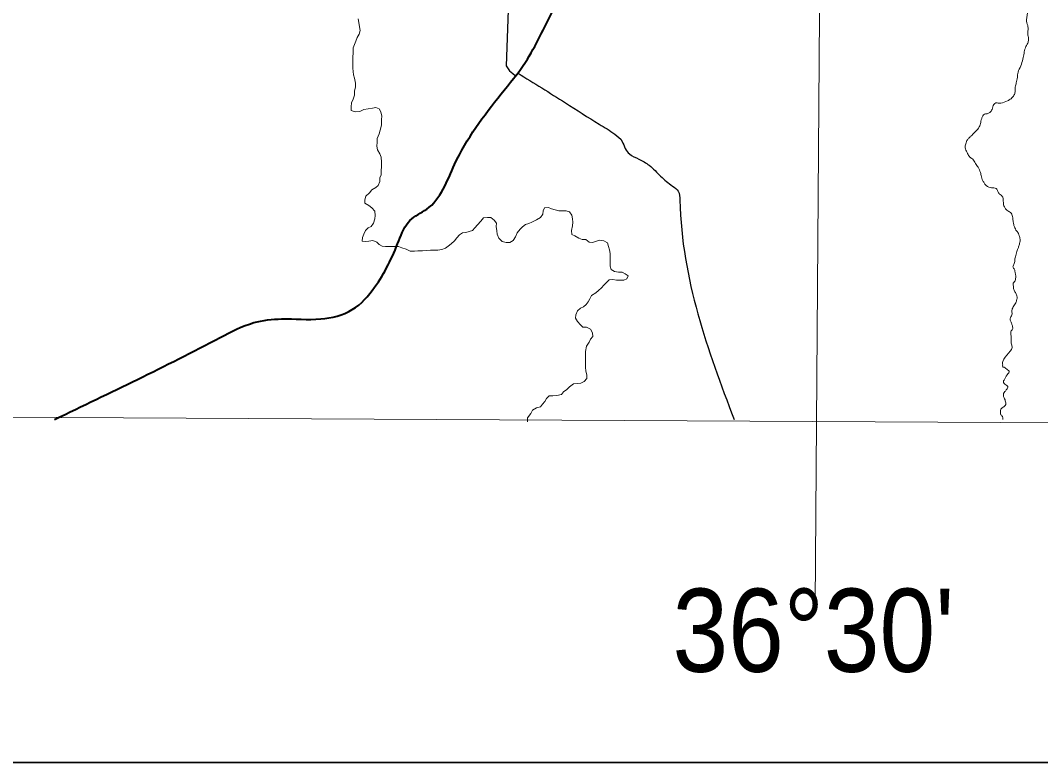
# Model space of a CAD drawing. Extents: x 553962 to 842807, y 8883888 to 9032388.
# Drawn here: x 616084 to 619151, y 8897728 to 8899960 of the extents above; entities that cross this region are included whole.
import ezdxf
from ezdxf.enums import TextEntityAlignment as Align

# ---------------------------------------------------------------- set-up
doc = ezdxf.new("R2010")
doc.units = 0
doc.header["$LTSCALE"] = 160
doc.layers.add('6', color=7, linetype='Continuous', lineweight=13)

msp = doc.modelspace()

# ---------------------------------------------------------------- linework, layer by layer
at = {"layer": '6', "lineweight": 35}
msp.add_lwpolyline([(576104.8, 8927170.9), (624533.7, 8927170.9), (624533.7, 8897728.1), (576104.8, 8897728.1)], close=True, dxfattribs=at)
at = {"layer": '6'}
for points in [[(618663, 8924716.1), (618558.3, 8909803.7), (618472.6, 8898203.5)], [(617099.6, 8899964.4), (617105.5, 8899929.8), (617102.3, 8899918.6), (617096.2, 8899908.4), (617092, 8899897.3), (617087.9, 8899887.1), (617083.7, 8899876.9), (617083.7, 8899865.7), (617083.5, 8899846.4), (617083.5, 8899836.2), (617083.4, 8899826), (617083.3, 8899815.8), (617085.2, 8899796.4), (617088.2, 8899786.2), (617091.1, 8899770.9), (617091.1, 8899759.7), (617087.9, 8899747.5), (617087.8, 8899735.3), (617083.7, 8899723.1), (617079.5, 8899711.9), (617078.4, 8899699.7), (617078.4, 8899688.5), (617090.6, 8899685.4), (617103.8, 8899686.3), (617116, 8899692.3), (617129.3, 8899694.3), (617142.5, 8899696.2), (617152.7, 8899698.2), (617161.8, 8899694.1), (617166.8, 8899684.9), (617169.8, 8899671.6), (617169.7, 8899661.4), (617169.6, 8899645.1), (617165.4, 8899629.9), (617162.3, 8899618.7), (617156.1, 8899604.5), (617156, 8899593.3), (617154.9, 8899582.1), (617156.9, 8899570.8), (617163.9, 8899558.6), (617167.9, 8899548.4), (617168.8, 8899533.1), (617168.8, 8899520.8), (617168.7, 8899507.6), (617168.6, 8899495.4), (617164.5, 8899486.2)], [(617164.5, 8899486.2), (617164.4, 8899475), (617159.5, 8899463.6), (617151.9, 8899457.9), (617139.8, 8899450.7), (617133.6, 8899441.6), (617122.4, 8899431.5), (617119.2, 8899420.3), (617119.2, 8899410.1), (617131.3, 8899402.9), (617140.4, 8899396.7), (617149.5, 8899386.5), (617150.5, 8899373.2), (617149.4, 8899363.1), (617145.2, 8899349.8), (617138, 8899339.7), (617128.8, 8899335.7), (617120.7, 8899328.6), (617116.5, 8899317.4), (617112.4, 8899307.3), (617111.3, 8899296.1), (617121.4, 8899295), (617131.6, 8899295.9), (617142.8, 8899297.9), (617155, 8899292.7), (617162.1, 8899285.6), (617171.2, 8899281.4), (617181.3, 8899280.3), (617195.6, 8899280.2), (617205.8, 8899280.2), (617220, 8899280.1), (617230.2, 8899275.9), (617243.3, 8899271.8), (617255.5, 8899265.6), (617268.7, 8899265.5), (617278.9, 8899266.5), (617292.1, 8899267.4)], [(617292.1, 8899267.4), (617304.3, 8899268.3), (617316.6, 8899269.3), (617327.8, 8899269.2), (617338.9, 8899269.1), (617350.2, 8899271.1), (617361.4, 8899275.1), (617369.5, 8899281.2), (617378.8, 8899288.2), (617389, 8899297.3), (617396.2, 8899306.5), (617403.3, 8899314.6), (617412.5, 8899320.6), (617422.7, 8899321.6), (617432.9, 8899325.6), (617443.1, 8899328.6), (617450.3, 8899335.7), (617457.5, 8899344.8), (617467.7, 8899355.9), (617475.9, 8899366.1), (617488.1, 8899367), (617498.3, 8899366.9), (617508.4, 8899358.7), (617514.5, 8899350.5), (617514.4, 8899340.3), (617516.3, 8899327.1), (617517.3, 8899316.9), (617522.3, 8899304.6), (617532.4, 8899295.4), (617543.6, 8899292.3), (617554.8, 8899292.2), (617565, 8899298.2), (617572.2, 8899309.4), (617577.3, 8899320.6), (617585.6, 8899331.7), (617592.7, 8899338.8), (617601.9, 8899345.9), (617612.1, 8899348.9), (617621.3, 8899352.9), (617635.6, 8899359.9), (617646.8, 8899367), (617654, 8899377.1), (617655.1, 8899387.3), (617659.2, 8899396.5), (617671.4, 8899397.4), (617680.6, 8899393.3), (617691.7, 8899390.1), (617701.9, 8899387), (617713.1, 8899386.9), (617724.3, 8899386.9), (617734.4, 8899383.8), (617741.5, 8899374.5), (617743.4, 8899363.3), (617744.4, 8899353.1), (617743.3, 8899341.9), (617740.1, 8899327.7), (617741.1, 8899316.5), (617750.2, 8899312.3), (617762.4, 8899305.1), (617772.5, 8899301), (617783.7, 8899300.9), (617793.8, 8899292.7), (617804, 8899291.6), (617815.2, 8899295.6), (617825.4, 8899298.6)], [(617825.4, 8899298.6), (617837.6, 8899297.5), (617848.7, 8899291.3), (617851.7, 8899280.1), (617854.7, 8899269.9), (617856.6, 8899258.7), (617856.6, 8899244.4), (617856.5, 8899233.2), (617856.4, 8899221), (617859.4, 8899210.8), (617869.5, 8899204.6), (617881.7, 8899202.5), (617892.9, 8899202.4), (617902, 8899198.3), (617911.1, 8899192.1), (617907, 8899183), (617897.8, 8899178.9), (617885.6, 8899179), (617875.4, 8899179.1), (617864.2, 8899181.2), (617854.1, 8899180.2), (617844.8, 8899171.1), (617837.7, 8899164.1), (617830.5, 8899155.9), (617821.3, 8899147.9), (617813.1, 8899140.8), (617800.8, 8899132.7), (617795.7, 8899122.6), (617790.5, 8899113.4), (617784.4, 8899105.3), (617776.2, 8899098.2), (617767, 8899094.2), (617758.8, 8899086.1), (617753.7, 8899074.9), (617752.6, 8899064.8), (617758.6, 8899054.5), (617767.7, 8899044.3)], [(617767.7, 8899044.3), (617774.8, 8899037.1), (617786, 8899037), (617797.1, 8899031.9), (617803.1, 8899020.6), (617804.1, 8899009.4), (617797.9, 8899001.3), (617793.8, 8898992.2), (617785.6, 8898980), (617782.4, 8898964.7), (617782.3, 8898952.5), (617782.2, 8898940.3), (617782.2, 8898928.1), (617782.1, 8898916.8), (617783, 8898905.6), (617787, 8898894.4), (617786.9, 8898883.2), (617778.7, 8898874.1), (617768.5, 8898869.1), (617757.3, 8898868.1), (617746.1, 8898867.2), (617733.9, 8898858.1), (617726.7, 8898850), (617716.5, 8898842.9), (617710.3, 8898834.8), (617696, 8898831.8), (617683.8, 8898830.9), (617673.7, 8898830.9), (617665.5, 8898822.9), (617660.3, 8898813.7), (617653.1, 8898805.6), (617647, 8898797.5), (617634.8, 8898794.5), (617623.5, 8898787.5), (617618.4, 8898778.3), (617608.1, 8898765.2), (617608, 8898753.2), (617608, 8898753.2), (617608.1, 8898765.2)], [(577181.5, 8898943.8), (596544.3, 8898870.4), (623547.8, 8898727.2)]]:
    msp.add_lwpolyline(points, dxfattribs=at)
at = {"layer": '6', "lineweight": 25}
msp.add_lwpolyline([(616832.2, 8902001.8), (616857.5, 8901964), (616879.7, 8901912), (616954.8, 8901814.1), (617016.6, 8901733.5), (617062.3, 8901691.6), (617085.6, 8901664.1), (617491.1, 8901095.8), (617501.2, 8901082.6), (617505.2, 8901061.2), (617519.8, 8900868.6), (617561, 8900712.6), (617580, 8900602.6), (617583.9, 8900553.7), (617583.7, 8900508.8), (617579.5, 8900483.4), (617569.1, 8900420.2), (617561.6, 8900327.5), (617544.5, 8899823.2), (617553.6, 8899807.9), (617563.8, 8899799.8), (617571, 8899793.8)], dxfattribs=at)
at = {"layer": '6', "lineweight": 40}
msp.add_spline([(616186.7, 8898760.2), (616684.4, 8899006.3), (616785.1, 8899051), (616869, 8899062.2), (616986.5, 8899062.2), (617081.5, 8899090.2), (617148.7, 8899157.3), (617221.3, 8899297.1), (617254.9, 8899358.6), (617305.2, 8899392.2), (617389.1, 8899526.4), (617529, 8899738.9), (617601.7, 8899834), (617685.6, 8899990.6), (617752.7, 8900091.3), (617853.4, 8900164), (618004.4, 8900197.6), (618194.5, 8900231.1), (618356.7, 8900225.5), (618479.8, 8900219.9), (618614, 8900152.8), (618703.5, 8900119.2), (618748.2, 8900113.7), (618832.1, 8900175.2), (618910.4, 8900231.1), (618977.5, 8900225.5), (619067, 8900203.2), (619100.6, 8900214.3), (619117.4, 8900253.5), (619106.2, 8900320.6), (619117.4, 8900421.3), (619106.2, 8900516.3), (619078.2, 8900566.7), (619095, 8900611.4), (619145.3, 8900723.3), (619229.2, 8900868.7), (619307.5, 8900958.2), (619380.2, 8901019.7), (619512.8, 8901031.2), (619643.1, 8901014.1), (619824.8, 8900993.8)], degree=3, dxfattribs=at)
at = {"layer": '6'}
for points in [[(618987.6, 8900189.8), (618996.9, 8900181.8), (619008.4, 8900178.3), (619017.7, 8900172.8), (619027.5, 8900168), (619048.1, 8900163.7), (619061.6, 8900160.7), (619076.2, 8900161.7), (619087, 8900160), (619101.8, 8900147.4), (619113.3, 8900130.3), (619118.6, 8900119), (619119.4, 8900104.7), (619122.6, 8900090.4), (619123.1, 8900075.6), (619125.1, 8900064.5), (619128.2, 8900055.8), (619123.4, 8900027.1), (619117.9, 8900002.3), (619112.3, 8899984.2), (619109.3, 8899970.4), (619108.6, 8899957.1), (619112.6, 8899940.5), (619112.6, 8899928.4), (619112.6, 8899915.9), (619114.3, 8899901.6), (619111.8, 8899891.5), (619104.8, 8899877.5), (619100.8, 8899861.2), (619097.3, 8899843.6), (619090.8, 8899823), (619083, 8899804.1), (619080.7, 8899788.8), (619077.5, 8899772.2), (619074.5, 8899759.4), (619074, 8899744.6), (619070.4, 8899734.6), (619061.7, 8899724.5), (619050.9, 8899718), (619031.3, 8899711), (619020.2, 8899711.5), (619015.7, 8899711.5), (619006.6, 8899700.3), (619004.6, 8899692), (618997.5, 8899683), (618990.3, 8899679.2), (618984.5, 8899678.7), (618979.2, 8899676), (618975.2, 8899669.2), (618972.2, 8899660.4), (618968.7, 8899646.3), (618961.9, 8899633.1), (618951.9, 8899622.8), (618942.1, 8899612.7), (618935.1, 8899605.9)], [(618935.1, 8899605.9), (618929.3, 8899598.9), (618926.3, 8899591.9), (618924, 8899579.6), (618924.8, 8899573.3), (618931.1, 8899559.6), (618937.8, 8899548.8), (618946.4, 8899542.5), (618955.1, 8899529.9), (618962.4, 8899518.1), (618969.7, 8899502.6), (618972.5, 8899489.8), (618974.7, 8899481.5), (618979.5, 8899473.2), (618984.2, 8899466.2), (618998.8, 8899457.1), (619013.8, 8899455.4), (619018.9, 8899452.4), (619022.6, 8899443.6), (619029.4, 8899436), (619036.9, 8899428.3), (619038.4, 8899419.5), (619039.4, 8899405.4), (619041.7, 8899399.1), (619046.9, 8899391.3), (619057.4, 8899384), (619062.2, 8899380), (619065.2, 8899373.7), (619066.7, 8899366.2), (619068, 8899353.9), (619069.7, 8899345.6), (619073.2, 8899336.6), (619076.5, 8899329.3), (619082.3, 8899322), (619085.5, 8899315.2), (619088.5, 8899305.4), (619088.8, 8899296.2), (619087.5, 8899289.1), (619084.5, 8899279.1), (619081.3, 8899271), (619079, 8899265), (619075, 8899248.7), (619073.2, 8899242.7), (619073.2, 8899237.2), (619072, 8899231.9), (619070, 8899225.6), (619067.7, 8899221.1), (619068.2, 8899216.8), (619071, 8899213.1), (619073.5, 8899205), (619075.5, 8899195.2), (619075.5, 8899184.2), (619073.7, 8899176.9), (619070, 8899171.9), (619067.7, 8899169.6)], [(619067.7, 8899169.6), (619068.7, 8899159.8), (619069.5, 8899153.6), (619073.5, 8899143.8), (619078, 8899134.7), (619079.7, 8899128), (619079, 8899120.7), (619075.7, 8899110.9), (619072.2, 8899104.6), (619068, 8899098.3), (619065.4, 8899092.3), (619064.2, 8899088), (619064.9, 8899077.1), (619063.4, 8899071.8), (619059.7, 8899065.8), (619058.9, 8899061.1), (619059.9, 8899056.3), (619063.7, 8899047.8), (619066.2, 8899038.7), (619066.9, 8899033.2), (619062.4, 8899026.7), (619060.7, 8899019.1), (619062.2, 8899009.1), (619061.7, 8898998.1), (619062.2, 8898989), (619064.2, 8898983), (619036.6, 8898934.3), (619035.8, 8898928.6), (619036.6, 8898924.1), (619036.6, 8898918.3), (619041.1, 8898916.8), (619051.1, 8898908.7), (619055.6, 8898905.5), (619050.1, 8898894.2), (619040.6, 8898877.9), (619038.6, 8898873.8), (619040.8, 8898868.1), (619045.6, 8898863.8), (619051.6, 8898859.3), (619050.9, 8898854.3), (619048.1, 8898850.5), (619043.3, 8898843.5), (619039.3, 8898837.7), (619038.8, 8898832.7), (619040.6, 8898825.1), (619043.8, 8898818.6), (619045.1, 8898813.1), (619046.1, 8898807.1), (619044.3, 8898802.1), (619035.1, 8898795), (619031.3, 8898791), (619029.6, 8898782), (619030.1, 8898776.4), (619035.6, 8898768.4), (619037.3, 8898760.1)]]:
    msp.add_spline(points, degree=3, dxfattribs=at)
at = {"layer": '6', "lineweight": 25}
msp.add_spline([(617579.8, 8899801), (617722.1, 8899711.9), (617823.8, 8899647.8), (617870.7, 8899618), (617892.6, 8899596.1), (617902, 8899574.2), (617914.5, 8899558.6), (617942.7, 8899542.9), (617974, 8899524.2), (618008.4, 8899491.3), (618044.3, 8899461.6), (618061.5, 8899446), (618066.2, 8899419.4), (618228.9, 8898759.8)], degree=3, dxfattribs=at)

# ---------------------------------------------------------------- texts
at = {"layer": '6', "width": 0.9}
msp.add_text("36°30'", height=250, dxfattribs=at).set_placement((618467.6, 8898001.1), align=Align.CENTER)

doc.saveas('drawing.dxf')
